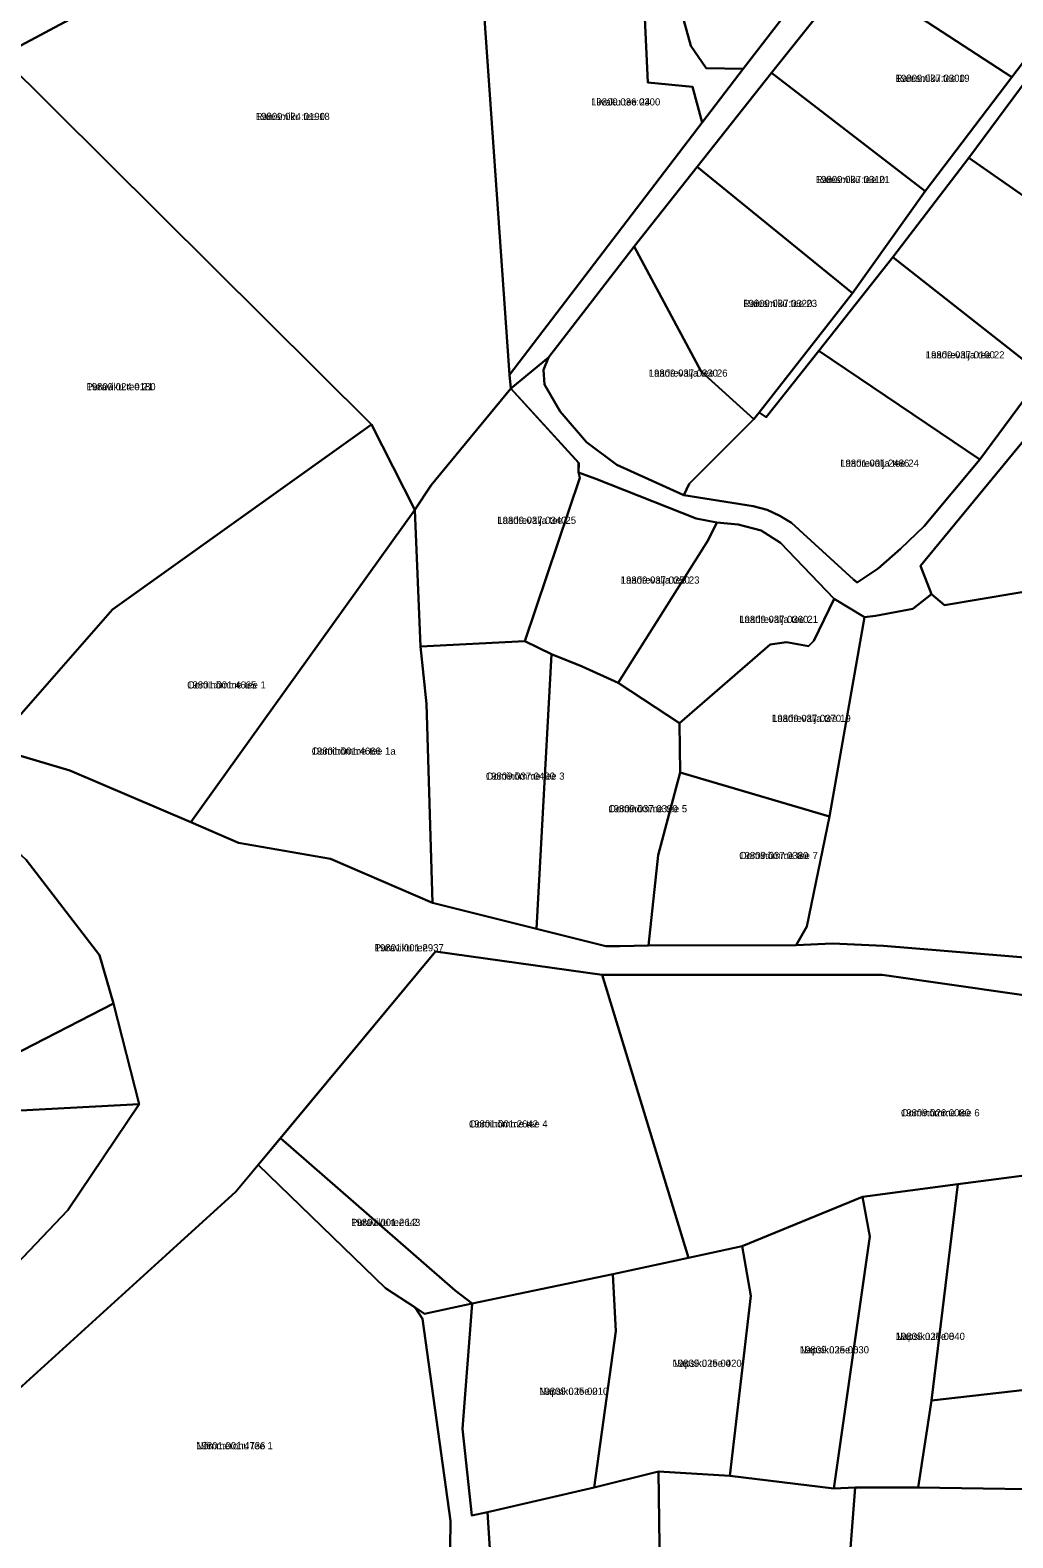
# Model space of a CAD drawing. Extents: x 516875 to 535633, y 6574491 to 6593094.
# Drawn here: x 521009.5 to 521215.5, y 6587635.9 to 6587952 of the extents above; entities that cross this region are included whole.
import ezdxf

# ---------------------------------------------------------------- set-up
doc = ezdxf.new("R2010")
doc.units = 0
for name, color, linetype in [('L_AADRESS', 7, 'Continuous'), ('PIIR', 7, 'Continuous'), ('TUNNUS', 7, 'Continuous')]:
    doc.layers.add(name, color=color, linetype=linetype)

msp = doc.modelspace()

# ---------------------------------------------------------------- linework, layer by layer
at = {"layer": 'PIIR'}
for points in [[(521003.07, 6588065.06), (521011.75, 6588048.53), (521025.21, 6588022.93), (521024.16, 6588021.59), (521037.14, 6587995.54), (521044.39, 6587980.33), (521047.68, 6587970.32), (521003.29, 6587946.56), (520997.73, 6587937.82), (520982.79, 6587914.49), (520972.17, 6587875.01), (520938.84, 6587839.12), (520937.21, 6587837.41), (520932.14, 6587839.34), (520938.49, 6587846.15), (520965.04, 6587879.05), (520976.62, 6587922.32), (520944.58, 6588043.32), (520999.32, 6588063.67)], [(521180.61, 6587971.98), (521158.93, 6587943.85), (521151.19, 6587943.99), (521147.96, 6587948.67), (521145.81, 6587956.49), (521142.39, 6587992.23)], [(521047.68, 6587970.32), (521073.48, 6587977.48), (521075.81, 6587978.05), (521100.44, 6587984.92), (521102.39, 6587986.18), (521103.77, 6587968.4), (521109.96, 6587879.72), (521110.27, 6587876.83), (521093.54, 6587856.57), (521090.13, 6587851.42), (521081.07, 6587869.33), (521003.29, 6587946.56)], [(521200.27, 6587987.77), (521231.42, 6587963.35), (521215.28, 6587942.14), (521181.69, 6587964.04)], [(521137.6, 6587971.07), (521138.98, 6587940.98), (521148.37, 6587940.11), (521150.38, 6587932.65), (521109.96, 6587879.72), (521103.77, 6587968.4)], [(521181.69, 6587964.04), (521215.28, 6587942.14), (521197.1, 6587918.25), (521164.92, 6587943.01)], [(521223.14, 6587947.9), (521254.61, 6587924.08), (521238.55, 6587902.7), (521206.25, 6587925.23)], [(520994.66, 6587803.64), (520986.75, 6587808.09), (520961.47, 6587827.71), (520975.06, 6587827.04), (520978.75, 6587840.51), (520972.17, 6587875.01), (520982.79, 6587914.49), (520997.73, 6587937.82), (521003.29, 6587946.56), (521081.07, 6587869.33), (521026.76, 6587830.55), (521005.72, 6587806.46)], [(521164.92, 6587943.01), (521197.1, 6587918.25), (521181.85, 6587896.84), (521149.3, 6587923.31)], [(521206.25, 6587925.23), (521238.55, 6587902.7), (521230.76, 6587894.66), (521221.72, 6587879.71), (521190.37, 6587904.4)], [(521136.08, 6587906.62), (521149.3, 6587923.31), (521181.85, 6587896.84), (521162.35, 6587871.82), (521161.23, 6587870.4), (521150.16, 6587880.45)], [(521126.12, 6587865.63), (521120.59, 6587872.07), (521117.32, 6587877.73), (521117.12, 6587880.8), (521118.15, 6587883.39), (521136.08, 6587906.62), (521150.16, 6587880.45), (521161.23, 6587870.4), (521147.64, 6587856.84), (521146.53, 6587854.5), (521132.49, 6587860.84)], [(521190.37, 6587904.4), (521221.72, 6587879.71), (521208.57, 6587861.94), (521174.85, 6587884.73)], [(521163.81, 6587870.86), (521174.85, 6587884.73), (521208.57, 6587861.94), (521196.92, 6587848.02), (521191.98, 6587843.27), (521187.25, 6587839.15), (521182.83, 6587836.2), (521182.08, 6587836.84), (521169.11, 6587848.69), (521166.65, 6587850.16), (521163.96, 6587851.44), (521161.08, 6587852.18), (521146.53, 6587854.5), (521147.64, 6587856.84), (521161.23, 6587870.4), (521162.35, 6587871.82)], [(521090.13, 6587851.42), (521093.54, 6587856.57), (521110.27, 6587876.83), (521124.49, 6587861.25), (521124.45, 6587859.28), (521124.7, 6587858.1), (521113.15, 6587823.86), (521091.28, 6587822.8)], [(521017.79, 6587796.78), (520994.66, 6587803.64), (521005.72, 6587806.46), (521026.76, 6587830.55), (521081.07, 6587869.33), (521090.13, 6587851.42), (521043.13, 6587785.92)], [(521198.47, 6587833.76), (521196.13, 6587839.69), (521218.38, 6587866.68), (521246.87, 6587850.38), (521238.56, 6587837.74), (521201.18, 6587831.42)], [(521118.74, 6587821.19), (521113.15, 6587823.86), (521124.7, 6587858.1), (521124.45, 6587859.28), (521128.07, 6587857.95), (521149.11, 6587849.64), (521153.42, 6587848.75), (521151.61, 6587845.05), (521132.73, 6587815.14), (521125.21, 6587818.56)], [(521043.13, 6587785.92), (521090.13, 6587851.42), (521091.28, 6587822.8), (521092.57, 6587810.78), (521093.84, 6587769.02), (521072.45, 6587778.25), (521053.12, 6587781.63)], [(521132.73, 6587815.14), (521151.61, 6587845.05), (521153.42, 6587848.75), (521157.9, 6587848.34), (521162.7, 6587847.09), (521166.77, 6587844.51), (521178.05, 6587832.76), (521173.8, 6587823.94), (521172.69, 6587822.81), (521168.03, 6587823.69), (521164.59, 6587823.16), (521145.59, 6587806.67)], [(521184.43, 6587828.89), (521186.73, 6587829.22), (521194.54, 6587830.65), (521198.47, 6587833.76), (521201.18, 6587831.42), (521238.56, 6587837.74), (521265.31, 6587815.39), (521273.46, 6587808.53), (521271.52, 6587804.36), (521254.25, 6587768.36), (521246.23, 6587751.58), (521220.58, 6587757.39), (521188.36, 6587760.02), (521177.71, 6587760.53), (521170.1, 6587760.17), (521172.33, 6587764.08), (521177.03, 6587787.15)], [(521145.59, 6587806.67), (521164.59, 6587823.16), (521168.03, 6587823.69), (521172.69, 6587822.81), (521173.8, 6587823.94), (521178.05, 6587832.76), (521184.43, 6587828.89), (521177.03, 6587787.15), (521145.77, 6587796.37)], [(521092.57, 6587810.78), (521091.28, 6587822.8), (521113.15, 6587823.86), (521118.74, 6587821.19), (521115.64, 6587763.6), (521093.84, 6587769.02)], [(521118.74, 6587821.19), (521125.21, 6587818.56), (521132.73, 6587815.14), (521145.59, 6587806.67), (521145.77, 6587796.37), (521141.14, 6587779.02), (521139.14, 6587760.06), (521133.12, 6587759.96), (521130.17, 6587759.98), (521115.64, 6587763.6)], [(520948.79, 6587768.52), (520965.98, 6587786.72), (520980.4, 6587801.99), (521000.03, 6587785.93), (521008.64, 6587778.02), (521024.01, 6587758.08), (521026.95, 6587747.91), (521005.47, 6587736.88), (520960.45, 6587735.92)], [(521141.14, 6587779.02), (521145.77, 6587796.37), (521177.03, 6587787.15), (521172.33, 6587764.08), (521170.1, 6587760.17), (521139.14, 6587760.06)], [(521094.47, 6587758.86), (521129.39, 6587753.93), (521147.49, 6587694.6), (521131.62, 6587691.19), (521102.12, 6587685.01), (521098.55, 6587687.74), (521061.94, 6587719.7)], [(521158.75, 6587697.02), (521147.49, 6587694.6), (521129.39, 6587753.93), (521188.07, 6587753.93), (521228.98, 6587748.06), (521244.21, 6587743.28), (521246.3, 6587715.54), (521203.94, 6587710.02), (521183.95, 6587707.43)], [(521026.95, 6587747.91), (521032.3, 6587726.8), (520940.56, 6587721.91), (520938.93, 6587729.62), (520938.78, 6587733.66), (520960.45, 6587735.92), (521005.47, 6587736.88)], [(520940.56, 6587721.91), (521032.3, 6587726.8), (521017.4, 6587704.6), (520985.07, 6587670.71), (520981.33, 6587682.08), (520946.63, 6587693.07)], [(521057.29, 6587714.11), (521061.94, 6587719.7), (521098.55, 6587687.74), (521102.12, 6587685.01), (521092.18, 6587682.89), (521090.18, 6587684.22), (521083.96, 6587688.23)], [(521052.62, 6587708.5), (521057.29, 6587714.11), (521083.96, 6587688.23), (521090.18, 6587684.22), (521091.75, 6587681.83), (521097.59, 6587639.48), (521097.18, 6587605.46), (521087.24, 6587604.22), (521011.71, 6587594.85), (521008.54, 6587599.9), (520980.59, 6587644.45), (520993.82, 6587655.11)], [(521198.46, 6587664.72), (521203.94, 6587710.02), (521246.3, 6587715.54), (521270.51, 6587683.54), (521226.68, 6587667.93)], [(521160.6, 6587686.63), (521158.75, 6587697.02), (521183.95, 6587707.43), (521185.54, 6587699.06), (521177.96, 6587646.27), (521156.15, 6587648.94)], [(521177.96, 6587646.27), (521185.54, 6587699.06), (521183.95, 6587707.43), (521203.94, 6587710.02), (521198.46, 6587664.72), (521195.66, 6587646.45), (521182.41, 6587646.46)], [(521127.7, 6587646.48), (521132.26, 6587679.23), (521131.62, 6587691.19), (521147.49, 6587694.6), (521158.75, 6587697.02), (521160.6, 6587686.63), (521156.15, 6587648.94), (521141.19, 6587649.82)], [(521102.07, 6587640.59), (521100.1, 6587658.75), (521102.12, 6587685.01), (521131.62, 6587691.19), (521132.26, 6587679.23), (521127.7, 6587646.48), (521105.37, 6587641.32)], [(521091.75, 6587681.83), (521090.18, 6587684.22), (521092.18, 6587682.89), (521102.12, 6587685.01), (521100.1, 6587658.75), (521102.07, 6587640.59), (521105.37, 6587641.32), (521107.12, 6587613.93), (521112.63, 6587607.08), (521104.36, 6587606.35), (521097.18, 6587605.46), (521097.59, 6587639.48)], [(521195.66, 6587646.45), (521198.46, 6587664.72), (521226.68, 6587667.93), (521270.51, 6587683.54), (521271.62, 6587681.93), (521282.44, 6587667.57), (521232.03, 6587645.92)], [(521107.12, 6587613.93), (521105.37, 6587641.32), (521127.7, 6587646.48), (521141.19, 6587649.82), (521141.79, 6587608.3), (521140.69, 6587584.15), (521134.55, 6587583.77), (521115.97, 6587603.53), (521112.63, 6587607.08)], [(521141.79, 6587608.3), (521141.19, 6587649.82), (521156.15, 6587648.94), (521177.96, 6587646.27), (521182.41, 6587646.46), (521179.72, 6587611.08), (521178.83, 6587595.76), (521140.69, 6587584.15)], [(521179.72, 6587611.08), (521182.41, 6587646.46), (521195.66, 6587646.45), (521232.03, 6587645.92), (521206.82, 6587600), (521203.6, 6587594.02), (521178.83, 6587595.76)]]:
    msp.add_lwpolyline(points, close=True, dxfattribs=at)
for points in [[(521181.69, 6587964.04), (521164.92, 6587943.01), (521149.3, 6587923.31), (521136.08, 6587906.62), (521118.15, 6587883.39), (521110.27, 6587876.83), (521109.96, 6587879.72), (521150.38, 6587932.65), (521158.93, 6587943.85), (521180.61, 6587971.98)], [(521145.81, 6587956.49), (521147.96, 6587948.67), (521151.19, 6587943.99), (521158.93, 6587943.85), (521150.38, 6587932.65), (521148.37, 6587940.11), (521138.98, 6587940.98), (521137.6, 6587971.07)], [(521237.28, 6587966.42), (521224.36, 6587950.23), (521223.14, 6587947.9), (521206.25, 6587925.23), (521190.37, 6587904.4), (521174.85, 6587884.73), (521163.81, 6587870.86), (521162.35, 6587871.82), (521181.85, 6587896.84), (521197.1, 6587918.25), (521215.28, 6587942.14), (521231.42, 6587963.35)], [(521218.38, 6587866.68), (521196.13, 6587839.69), (521198.47, 6587833.76), (521194.54, 6587830.65), (521186.73, 6587829.22), (521184.43, 6587828.89), (521178.05, 6587832.76), (521166.77, 6587844.51), (521162.7, 6587847.09), (521157.9, 6587848.34), (521153.42, 6587848.75), (521149.11, 6587849.64), (521128.07, 6587857.95), (521124.45, 6587859.28), (521124.45, 6587861.28), (521110.27, 6587876.83), (521118.15, 6587883.39), (521117.12, 6587880.8), (521117.32, 6587877.73), (521120.59, 6587872.07), (521126.12, 6587865.63), (521132.49, 6587860.84), (521146.53, 6587854.5), (521161.08, 6587852.18), (521163.96, 6587851.44), (521166.65, 6587850.16), (521169.11, 6587848.69), (521182.08, 6587836.84), (521182.83, 6587836.2), (521187.25, 6587839.15), (521191.98, 6587843.27), (521196.92, 6587848.02), (521208.57, 6587861.94), (521221.72, 6587879.71)], [(520994.66, 6587803.64), (521017.79, 6587796.78), (521043.13, 6587785.92), (521053.12, 6587781.63), (521072.45, 6587778.25), (521093.84, 6587769.02), (521115.64, 6587763.6), (521130.17, 6587759.98), (521133.12, 6587759.96), (521139.14, 6587760.06), (521170.1, 6587760.17), (521177.71, 6587760.53), (521188.36, 6587760.02), (521220.58, 6587757.39)], [(520985.07, 6587670.71), (521017.4, 6587704.6), (521032.3, 6587726.8), (521026.95, 6587747.91), (521024.01, 6587758.08), (521008.64, 6587778.02)], [(521228.98, 6587748.06), (521188.07, 6587753.93), (521129.39, 6587753.93), (521094.47, 6587758.86), (521052.61, 6587708.47), (520993.94, 6587655.19)]]:
    msp.add_lwpolyline(points, dxfattribs=at)

# ---------------------------------------------------------------- texts
at = {"layer": 'L_AADRESS'}
for s, p in [('Raiesmiku tee 19', (521190.93, 6587941.15)), ('Liivaku tee 24', (521127.08, 6587936.19)), ('Raiesmiku tee 18', (521056.78, 6587933.15)), ('Raiesmiku tee 21', (521174.19, 6587919.93)), ('Raiesmiku tee 23', (521158.96, 6587893.95)), ('Laadrevälja tee 22', (521197.24, 6587883.17)), ('Laadrevälja tee 26', (521139.17, 6587879.34)), ('Puraviku tee 21', (521021.27, 6587876.49)), ('Laadrevälja tee 24', (521179.3, 6587860.46)), ('Laadrevälja tee 25', (521107.42, 6587848.48)), ('Laadrevälja tee 23', (521133.29, 6587835.95)), ('Laadrevälja tee 21', (521158.14, 6587827.71)), ('Oominõmme tee 1', (521042.39, 6587813.97)), ('Laadrevälja tee 19', (521165.01, 6587806.96)), ('Oominõmme tee 1a', (521068.49, 6587800.1)), ('Oominõmme tee 3', (521105.01, 6587794.85)), ('Oominõmme tee 5', (521130.71, 6587788.02)), ('Oominõmme tee 7', (521158.13, 6587778.21)), ('Puraviku tee', (521081.69, 6587758.87)), ('Oominõmme tee 4', (521101.47, 6587721.94)), ('Oominõmme tee 6', (521192.04, 6587724.27)), ('Puraviku tee L2', (521076.76, 6587701.29)), ('Napsiku tee 8', (521190.95, 6587677.4)), ('Napsiku tee 6', (521170.84, 6587674.58)), ('Napsiku tee 4', (521144.15, 6587671.76)), ('Napsiku tee 2', (521116.18, 6587665.89)), ('Nõmmerohu tee 1', (521044.28, 6587654.48))]:
    msp.add_text(s, height=1.5, dxfattribs=at).set_placement(p)
at = {"layer": 'TUNNUS'}
for s, p in [('19809:037:0300', (521190.93, 6587941.15)), ('19809:024:0190', (521056.78, 6587933.15)), ('19809:036:0300', (521127.08, 6587936.19)), ('19809:037:0310', (521174.19, 6587919.93)), ('19809:037:0320', (521158.96, 6587893.95)), ('19809:037:0100', (521197.24, 6587883.17)), ('19809:037:0330', (521139.17, 6587879.34)), ('19809:024:0180', (521021.27, 6587876.49)), ('19801:001:2486', (521179.3, 6587860.46)), ('19809:037:0340', (521107.42, 6587848.48)), ('19809:037:0350', (521133.29, 6587835.95)), ('19809:037:0360', (521158.14, 6587827.71)), ('19801:001:4665', (521042.39, 6587813.97)), ('19809:037:0370', (521165.01, 6587806.96)), ('19801:001:4666', (521068.49, 6587800.1)), ('19809:037:0400', (521105.01, 6587794.85)), ('19809:037:0390', (521130.71, 6587788.02)), ('19809:037:0380', (521158.13, 6587778.21)), ('19801:001:2937', (521081.69, 6587758.87)), ('19801:001:2642', (521101.47, 6587721.94)), ('19809:026:0080', (521192.04, 6587724.27)), ('19801:001:2643', (521076.76, 6587701.29)), ('19809:025:0040', (521190.95, 6587677.4)), ('19809:025:0030', (521170.84, 6587674.58)), ('19809:025:0020', (521144.15, 6587671.76)), ('19809:025:0010', (521116.18, 6587665.89)), ('19801:001:4736', (521044.28, 6587654.48))]:
    msp.add_text(s, height=1.5, dxfattribs=at).set_placement(p)

doc.saveas('drawing.dxf')
